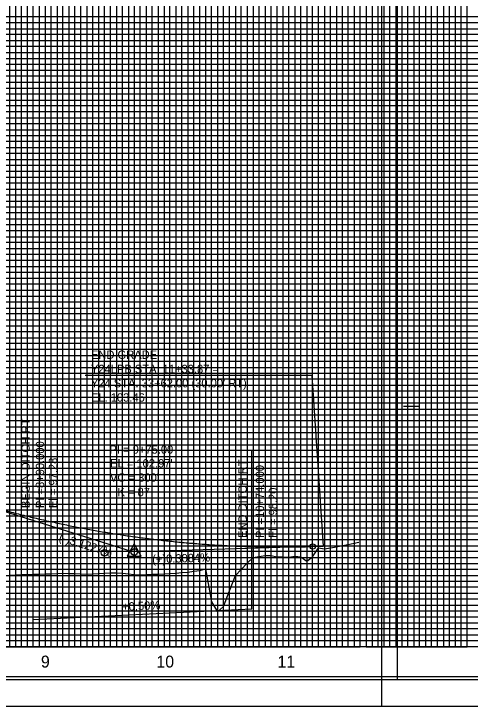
# Model space of a CAD drawing. Extents: x 2345490 to 2436403, y 465165 to 573888.
# Drawn here: x 2411769 to 2412153, y 532446 to 533028 of the extents above; entities that cross this region are included whole.
import ezdxf

# ---------------------------------------------------------------- set-up
doc = ezdxf.new("R2010")
doc.units = 0
for name, color, linetype in [('Old_Level_1', 7, 'Continuous'), ('Old_Level_18', 7, 'Continuous'), ('Old_Level_2', 7, 'Continuous'), ('Old_Level_3', 7, 'Continuous'), ('Old_Level_41', 7, 'Continuous'), ('Old_Level_42', 7, 'Continuous'), ('Old_Level_43', 7, 'Continuous'), ('Old_Level_50', 7, 'Continuous'), ('Old_Level_51', 7, 'Continuous'), ('Old_Level_52', 7, 'Continuous'), ('Old_Level_62', 7, 'Continuous'), ('Old_Level_63', 7, 'Continuous')]:
    doc.layers.add(name, color=color, linetype=linetype)

msp = doc.modelspace()

# ---------------------------------------------------------------- linework, layer by layer
at = {"layer": 'Old_Level_1'}
for points in [[(2411895.325, 532556.85825), (2411900.325, 532557.108), (2411905.325, 532557.51525), (2411910.325, 532557.9225), (2411915.325, 532558.32975), (2411920.325, 532559.0335), (2411925.325, 532559.82575), (2411930.325, 532561.1485), (2411935.325, 532533.47425), (2411940.325, 532525.0015), (2411945.325, 532529.461), (2411950.325, 532542.52475), (2411955.325, 532555.5885), (2411960.325, 532560.59275), (2411965.325, 532565.9155), (2411970.325, 532570.771), (2411975.325, 532571.51625), (2411980.325, 532572.2615), (2411985.325, 532572.44975), (2411990.325, 532571.2615), (2411995.325, 532571.30775), (2412000.325, 532571.033), (2412005.325, 532571.77175), (2412010.325, 532571.3365), (2412015.325, 532567.4515), (2412020.325, 532571.3345), (2412025.325, 532578.781), (2412030.325, 532578.0145), (2412035.325, 532578.869), (2412040.325, 532579.75475), (2412045.325, 532580.64075), (2412050.325, 532581.5265), (2412055.325, 532582.6855), (2412059.195, 532583.5655)], [(2411765.325, 532555.92575), (2411770.325, 532556.10975), (2411775.325, 532556.278), (2411780.325, 532556.40175), (2411785.325, 532556.527), (2411790.325, 532556.66025), (2411795.325, 532556.8405), (2411800.325, 532557.022), (2411805.325, 532557.205), (2411810.325, 532557.39075), (2411815.325, 532557.24025), (2411820.325, 532557.0725), (2411825.325, 532556.90675), (2411830.325, 532556.74225), (2411835.325, 532556.8855), (2411840.325, 532557.17725), (2411845.325, 532557.47), (2411850.325, 532557.7635), (2411855.325, 532557.81475), (2411860.325, 532557.381), (2411865.325, 532556.92175), (2411870.325, 532556.46325), (2411875.325, 532556.15), (2411880.325, 532556.327), (2411885.325, 532556.50425), (2411890.325, 532556.68125), (2411895.325, 532556.85825)]]:
    msp.add_lwpolyline(points, dxfattribs=at)
at = {"layer": 'Old_Level_18'}
msp.add_lwpolyline([(2412345.325, 533520.5875), (2410845.325, 533520.5875), (2410845.325, 532470.5875), (2412345.325, 532470.5875)], close=True, dxfattribs=at)
at = {"layer": 'Old_Level_2'}
for p, q in [((2412019.7535, 532723.708), (2411829.07475, 532723.708)), ((2412019.7535, 532723.708), (2412029.195, 532580.1875)), ((2411720.325, 532622.1275), (2411867.70025, 532576.10725)), ((2412020.325, 532579.914), (2411873.07375, 532575.3725)), ((2412020.325, 532579.914), (2412029.195, 532580.1875))]:
    msp.add_line(p, q, dxfattribs=at)
msp.add_lwpolyline([(2411864.45375, 532571.91225), (2411876.19625, 532571.91225), (2411870.32525, 532582.038)], close=True, dxfattribs=at)
for centre, radius in [((2412020.325, 532579.914), 2.25), ((2411845.325, 532574.5875), 2.75), ((2411870.325, 532575.2875), 2.75)]:
    msp.add_circle(centre, radius, dxfattribs=at)
msp.add_spline([(2411720.325, 532622.1275), (2411726.325, 532620.2745), (2411732.325, 532618.46275), (2411738.325, 532616.692), (2411744.325, 532614.9625), (2411750.325, 532613.27425), (2411756.325, 532611.62725), (2411762.325, 532610.02125), (2411768.325, 532608.45625), (2411774.325, 532606.93275), (2411780.325, 532605.45025), (2411786.325, 532604.009), (2411792.325, 532602.609), (2411798.325, 532601.25), (2411804.325, 532599.93225), (2411810.325, 532598.6555), (2411816.325, 532597.42025), (2411822.325, 532596.226), (2411828.325, 532595.07275), (2411834.325, 532593.961), (2411840.325, 532592.89025), (2411846.325, 532591.86075), (2411852.325, 532590.87225), (2411858.325, 532589.925), (2411864.325, 532589.019), (2411870.325, 532588.15425), (2411876.325, 532587.3305), (2411882.325, 532586.548), (2411888.325, 532585.80675), (2411894.325, 532585.1065), (2411900.325, 532584.4475), (2411906.325, 532583.82975), (2411912.325, 532583.253), (2411918.325, 532582.7175), (2411924.325, 532582.22325), (2411930.325, 532581.77025), (2411936.325, 532581.35825), (2411942.325, 532580.9875), (2411948.325, 532580.65775), (2411954.325, 532580.3695), (2411960.325, 532580.12225), (2411966.325, 532579.916), (2411972.325, 532579.75125), (2411978.325, 532579.6275), (2411984.325, 532579.54475), (2411990.325, 532579.5035), (2411996.325, 532579.50325), (2412002.325, 532579.54425), (2412008.325, 532579.62625), (2412014.325, 532579.7495), (2412020.325, 532579.914)], degree=3, dxfattribs=at)
at = {"layer": 'Old_Level_3'}
for p, q in [((2411785.325, 532518.3875), (2411785.325, 532693.32339)), ((2411969.325, 532600.02989), (2411969.325, 532661.04346)), ((2411969.325, 532527.5875), (2411969.325, 532600.02989)), ((2411785.325, 532518.3875), (2411969.325, 532527.5875))]:
    msp.add_line(p, q, dxfattribs=at)
at = {"layer": 'Old_Level_41'}
for p, q in [((2412096.825, 532698.0875), (2412109.325, 532698.0875)), ((2412345.325, 532495.5875), (2410845.325, 532495.5875))]:
    msp.add_line(p, q, dxfattribs=at)
for points in [[(2411770.325, 533520.5875), (2411770.325, 532495.5875), (2411820.325, 532495.5875), (2411820.325, 533520.5875)], [(2411795.325, 533520.5875), (2411795.325, 532495.5875), (2411845.325, 532495.5875), (2411845.325, 533520.5875)], [(2411870.325, 533520.5875), (2411870.325, 532495.5875), (2411920.325, 532495.5875), (2411920.325, 533520.5875)], [(2411895.325, 533520.5875), (2411895.325, 532495.5875), (2411945.325, 532495.5875), (2411945.325, 533520.5875)], [(2411970.325, 533520.5875), (2411970.325, 532495.5875), (2412020.325, 532495.5875), (2412020.325, 533520.5875)], [(2411995.325, 533520.5875), (2411995.325, 532495.5875), (2412045.325, 532495.5875), (2412045.325, 533520.5875)], [(2412070.325, 533520.5875), (2412070.325, 532495.5875), (2412120.325, 532495.5875), (2412120.325, 533520.5875)], [(2412095.325, 533520.5875), (2412095.325, 532495.5875), (2412145.325, 532495.5875), (2412145.325, 533520.5875)], [(2412345.325, 533020.5875), (2410845.325, 533020.5875), (2410845.325, 532970.5875), (2412345.325, 532970.5875)], [(2412345.325, 532920.5875), (2410845.325, 532920.5875), (2410845.325, 532870.5875), (2412345.325, 532870.5875)], [(2412345.325, 532845.5875), (2410845.325, 532845.5875), (2410845.325, 532895.5875), (2412345.325, 532895.5875)], [(2412345.325, 532820.5875), (2410845.325, 532820.5875), (2410845.325, 532770.5875), (2412345.325, 532770.5875)], [(2412345.325, 532745.5875), (2410845.325, 532745.5875), (2410845.325, 532795.5875), (2412345.325, 532795.5875)], [(2412345.325, 532720.5875), (2410845.325, 532720.5875), (2410845.325, 532670.5875), (2412345.325, 532670.5875)], [(2412345.325, 532620.5875), (2410845.325, 532620.5875), (2410845.325, 532570.5875), (2412345.325, 532570.5875)], [(2412345.325, 532545.5875), (2410845.325, 532545.5875), (2410845.325, 532595.5875), (2412345.325, 532595.5875)], [(2412345.325, 532520.5875), (2410845.325, 532520.5875)]]:
    msp.add_lwpolyline(points, dxfattribs=at)
at = {"layer": 'Old_Level_42'}
for points in [[(2412345.325, 532945.5875), (2410845.325, 532945.5875), (2410845.325, 532995.5875), (2412345.325, 532995.5875)], [(2412345.325, 532645.5875), (2410845.325, 532645.5875), (2410845.325, 532695.5875), (2412345.325, 532695.5875)]]:
    msp.add_lwpolyline(points, dxfattribs=at)
at = {"layer": 'Old_Level_43'}
for points in [[(2411765.325, 533520.5875), (2411765.325, 532495.5875), (2411775.325, 532495.5875), (2411775.325, 533520.5875)], [(2411780.325, 533520.5875), (2411780.325, 532495.5875), (2411785.325, 532495.5875), (2411785.325, 533520.5875)], [(2411790.325, 533520.5875), (2411790.325, 532495.5875), (2411800.325, 532495.5875), (2411800.325, 533520.5875)], [(2411805.325, 533520.5875), (2411805.325, 532495.5875), (2411810.325, 532495.5875), (2411810.325, 533520.5875)], [(2411815.325, 533520.5875), (2411815.325, 532495.5875), (2411825.325, 532495.5875), (2411825.325, 533520.5875)], [(2411830.325, 533520.5875), (2411830.325, 532495.5875), (2411835.325, 532495.5875), (2411835.325, 533520.5875)], [(2411840.325, 533520.5875), (2411840.325, 532495.5875), (2411850.325, 532495.5875), (2411850.325, 533520.5875)], [(2411855.325, 533520.5875), (2411855.325, 532495.5875), (2411860.325, 532495.5875), (2411860.325, 533520.5875)], [(2411865.325, 533520.5875), (2411865.325, 532495.5875), (2411875.325, 532495.5875), (2411875.325, 533520.5875)], [(2411880.325, 533520.5875), (2411880.325, 532495.5875), (2411885.325, 532495.5875), (2411885.325, 533520.5875)], [(2411890.325, 533520.5875), (2411890.325, 532495.5875), (2411900.325, 532495.5875), (2411900.325, 533520.5875)], [(2411905.325, 533520.5875), (2411905.325, 532495.5875), (2411910.325, 532495.5875), (2411910.325, 533520.5875)], [(2411915.325, 533520.5875), (2411915.325, 532495.5875)], [(2411915.325, 532495.5875), (2411925.325, 532495.5875), (2411925.325, 533520.5875)], [(2411930.325, 533520.5875), (2411930.325, 532495.5875), (2411935.325, 532495.5875), (2411935.325, 533520.5875)], [(2411940.325, 533520.5875), (2411940.325, 532495.5875), (2411950.325, 532495.5875), (2411950.325, 533520.5875)], [(2411955.325, 533520.5875), (2411955.325, 532495.5875), (2411960.325, 532495.5875), (2411960.325, 533520.5875)], [(2411965.325, 533520.5875), (2411965.325, 532495.5875), (2411975.325, 532495.5875), (2411975.325, 533520.5875)], [(2411980.325, 533520.5875), (2411980.325, 532495.5875), (2411985.325, 532495.5875), (2411985.325, 533520.5875)], [(2411990.325, 533520.5875), (2411990.325, 532495.5875), (2412000.325, 532495.5875), (2412000.325, 533520.5875)], [(2412005.325, 533520.5875), (2412005.325, 532495.5875), (2412010.325, 532495.5875), (2412010.325, 533520.5875)], [(2412015.325, 533520.5875), (2412015.325, 532495.5875), (2412025.325, 532495.5875), (2412025.325, 533520.5875)], [(2412030.325, 533520.5875), (2412030.325, 532495.5875), (2412035.325, 532495.5875), (2412035.325, 533520.5875)], [(2412040.325, 533520.5875), (2412040.325, 532495.5875), (2412050.325, 532495.5875), (2412050.325, 533520.5875)], [(2412055.325, 533520.5875), (2412055.325, 532495.5875), (2412060.325, 532495.5875), (2412060.325, 533520.5875)], [(2412065.325, 533520.5875), (2412065.325, 532495.5875), (2412075.325, 532495.5875), (2412075.325, 533520.5875)], [(2412080.325, 533520.5875), (2412080.325, 532495.5875), (2412085.325, 532495.5875), (2412085.325, 533520.5875)], [(2412090.325, 533520.5875), (2412090.325, 532495.5875), (2412100.325, 532495.5875), (2412100.325, 533520.5875)], [(2412105.325, 533520.5875), (2412105.325, 532495.5875), (2412110.325, 532495.5875), (2412110.325, 533520.5875)], [(2412115.325, 533520.5875), (2412115.325, 532495.5875), (2412125.325, 532495.5875), (2412125.325, 533520.5875)], [(2412130.325, 533520.5875), (2412130.325, 532495.5875), (2412135.325, 532495.5875), (2412135.325, 533520.5875)], [(2412140.325, 533520.5875), (2412140.325, 532495.5875), (2412150.325, 532495.5875), (2412150.325, 533383.0375)], [(2412295.325, 533025.5875), (2410895.325, 533025.5875), (2410895.325, 533015.5875), (2412295.325, 533015.5875)], [(2412295.325, 533010.5875), (2410895.325, 533010.5875), (2410895.325, 533005.5875), (2412295.325, 533005.5875)], [(2412295.325, 533000.5875), (2410895.325, 533000.5875)], [(2410895.325, 532990.5875), (2412295.325, 532990.5875)], [(2412295.325, 532985.5875), (2410895.325, 532985.5875), (2410895.325, 532980.5875), (2412295.325, 532980.5875)], [(2412295.325, 532975.5875), (2410895.325, 532975.5875), (2410895.325, 532965.5875), (2412295.325, 532965.5875)], [(2412295.325, 532960.5875), (2410895.325, 532960.5875), (2410895.325, 532955.5875), (2412295.325, 532955.5875)], [(2412295.325, 532950.5875), (2410895.325, 532950.5875), (2410895.325, 532940.5875), (2412295.325, 532940.5875)], [(2412295.325, 532935.5875), (2410895.325, 532935.5875), (2410895.325, 532930.5875), (2412295.325, 532930.5875)], [(2412295.325, 532925.5875), (2410895.325, 532925.5875), (2410895.325, 532915.5875), (2412295.325, 532915.5875)], [(2412295.325, 532910.5875), (2410895.325, 532910.5875), (2410895.325, 532905.5875), (2412295.325, 532905.5875)], [(2412295.325, 532900.5875), (2410895.325, 532900.5875), (2410895.325, 532890.5875), (2412295.325, 532890.5875)], [(2412295.325, 532885.5875), (2410895.325, 532885.5875), (2410895.325, 532880.5875), (2412295.325, 532880.5875)], [(2412295.325, 532875.5875), (2410895.325, 532875.5875), (2410895.325, 532865.5875), (2412295.325, 532865.5875)], [(2412295.325, 532860.5875), (2410895.325, 532860.5875), (2410895.325, 532855.5875), (2412295.325, 532855.5875)], [(2412295.325, 532850.5875), (2410895.325, 532850.5875), (2410895.325, 532840.5875), (2412295.325, 532840.5875)], [(2412295.325, 532835.5875), (2410895.325, 532835.5875), (2410895.325, 532830.5875), (2412295.325, 532830.5875)], [(2412295.325, 532825.5875), (2410895.325, 532825.5875), (2410895.325, 532815.5875), (2412295.325, 532815.5875)], [(2412295.325, 532810.5875), (2410895.325, 532810.5875), (2410895.325, 532805.5875), (2412295.325, 532805.5875)], [(2412295.325, 532800.5875), (2410895.325, 532800.5875), (2410895.325, 532790.5875), (2412295.325, 532790.5875)], [(2412295.325, 532785.5875), (2410895.325, 532785.5875), (2410895.325, 532780.5875), (2412295.325, 532780.5875)], [(2412295.325, 532775.5875), (2410895.325, 532775.5875), (2410895.325, 532765.5875), (2412295.325, 532765.5875)], [(2412295.325, 532760.5875), (2410895.325, 532760.5875), (2410895.325, 532755.5875), (2412295.325, 532755.5875)], [(2412295.325, 532750.5875), (2410895.325, 532750.5875), (2410895.325, 532740.5875), (2412295.325, 532740.5875)], [(2412295.325, 532735.5875), (2410895.325, 532735.5875), (2410895.325, 532730.5875), (2412295.325, 532730.5875)], [(2412295.325, 532725.5875), (2410895.325, 532725.5875), (2410895.325, 532715.5875), (2412295.325, 532715.5875)], [(2412295.325, 532710.5875), (2410895.325, 532710.5875), (2410895.325, 532705.5875), (2412295.325, 532705.5875)], [(2412295.325, 532700.5875), (2410895.325, 532700.5875)], [(2410895.325, 532690.5875), (2412295.325, 532690.5875)], [(2412295.325, 532685.5875), (2410895.325, 532685.5875), (2410895.325, 532680.5875), (2412295.325, 532680.5875)], [(2412295.325, 532675.5875), (2410895.325, 532675.5875)], [(2410895.325, 532665.5875), (2412295.325, 532665.5875)], [(2412295.325, 532660.5875), (2410895.325, 532660.5875), (2410895.325, 532655.5875), (2412295.325, 532655.5875)], [(2412295.325, 532650.5875), (2410895.325, 532650.5875), (2410895.325, 532640.5875), (2412295.325, 532640.5875)], [(2412295.325, 532635.5875), (2410895.325, 532635.5875), (2410895.325, 532630.5875), (2412295.325, 532630.5875)], [(2412295.325, 532625.5875), (2410895.325, 532625.5875), (2410895.325, 532615.5875), (2412295.325, 532615.5875)], [(2412295.325, 532610.5875), (2410895.325, 532610.5875), (2410895.325, 532605.5875), (2412295.325, 532605.5875)], [(2412295.325, 532600.5875), (2410895.325, 532600.5875), (2410895.325, 532590.5875), (2412295.325, 532590.5875)], [(2412295.325, 532585.5875), (2410895.325, 532585.5875), (2410895.325, 532580.5875), (2412295.325, 532580.5875)], [(2412295.325, 532575.5875), (2410895.325, 532575.5875), (2410895.325, 532565.5875), (2412295.325, 532565.5875)], [(2412295.325, 532560.5875), (2410895.325, 532560.5875), (2410895.325, 532555.5875), (2412295.325, 532555.5875)], [(2412295.325, 532550.5875), (2410895.325, 532550.5875), (2410895.325, 532540.5875), (2412295.325, 532540.5875)], [(2412295.325, 532535.5875), (2410895.325, 532535.5875), (2410895.325, 532530.5875), (2412295.325, 532530.5875)], [(2412295.325, 532525.5875), (2410895.325, 532525.5875), (2410895.325, 532515.5875), (2412295.325, 532515.5875)], [(2412295.325, 532510.5875), (2410895.325, 532510.5875), (2410895.325, 532505.5875), (2412295.325, 532505.5875)], [(2412295.325, 532500.5875), (2410895.325, 532500.5875)]]:
    msp.add_lwpolyline(points, dxfattribs=at)
at = {"layer": 'Old_Level_50'}
msp.add_line((2412078.325, 532445.5875), (2412078.325, 532445.5875), dxfattribs=at)
for points in [[(2412357.825, 533523.1375), (2410691.325, 533523.1375), (2410691.325, 532468.0375), (2412357.825, 532468.0375)], [(2413757.825, 533523.1375), (2412091.325, 533523.1375), (2412091.325, 532468.0375), (2413757.825, 532468.0375)]]:
    msp.add_lwpolyline(points, close=True, dxfattribs=at)
at = {"layer": 'Old_Level_51'}
for points in [[(2412362.325, 533545.5875), (2410678.325, 533545.5875), (2410678.325, 532445.5875), (2412362.325, 532445.5875)], [(2413762.325, 533545.5875), (2412078.325, 533545.5875), (2412078.325, 532445.5875), (2413762.325, 532445.5875)]]:
    msp.add_lwpolyline(points, close=True, dxfattribs=at)
at = {"layer": 'Old_Level_52'}
msp.add_line((2412091.325, 532468.0375), (2412091.325, 532468.0375), dxfattribs=at)
at = {"layer": 'Old_Level_63'}
msp.add_line((2410895.325, 532495.5875), (2412059.1905, 532495.5875), dxfattribs=at)

# ---------------------------------------------------------------- texts
at = {"layer": 'Old_Level_2'}
for s, height, p in [('END GRADE', 7.000001, (2411833.85075, 532737.8165)), ('Y24LPB STA. 11+33.87 =', 7.0000005, (2411833.85075, 532725.8165)), ("Y24 STA. 33+62.00 (30.00' RT)", 7.0000005, (2411833.85075, 532713.8165)), ('EL. 103.46', 7.000001, (2411833.85075, 532701.8165)), ('PI = 9+75.00', 7.0000005, (2411849.46775, 532658.0305)), ("EL = 102.97'", 7.0000005, (2411849.9915, 532646.41375)), ("VC = 300'", 7.000001, (2411849.89725, 532634.462)), ('K = 87', 7.000001, (2411856.18275, 532622.263))]:
    msp.add_text(s, height=height, dxfattribs=at).set_placement(p)
for s, rotation, p in [('(-)3.1227%', 342.65815556, (2411806.38575, 532584.77775)), ('(+)0.3084%', 1.76660278, (2411885.49725, 532565.751))]:
    msp.add_text(s, height=7.000001, rotation=rotation, dxfattribs=at).set_placement(p)
at = {"layer": 'Old_Level_3'}
for s, height, rotation, p in [('BEGIN DITCH RT', 7.0000005, 90, (2411782.35653, 532612.235)), ('PI =8+90.000', 7.0000005, 90, (2411794.4624, 532612.235)), ('El = 97.28', 7.000001, 90, (2411805.4624, 532612.235)), ('END DITCH RT', 7.0000005, 90, (2411964.90383, 532587.05433)), ('PI =10+74.000', 7.0000005, 90, (2411979.43087, 532587.05433)), ('El = 98.20', 7.000001, 90, (2411990.43087, 532587.05433)), ('+0.50%', 7.000001, 2.8624, (2411860.31525, 532525.68825))]:
    msp.add_text(s, height=height, rotation=rotation, dxfattribs=at).set_placement(p)
at = {"layer": 'Old_Level_62'}
for s, height, p in [('9', 10, (2411791.79025, 532478.0875)), ('10', 10.000001, (2411888.9085, 532478.0875)), ('11', 10.000001, (2411990.748, 532478.0875))]:
    msp.add_text(s, height=height, dxfattribs=at).set_placement(p)

doc.saveas('drawing.dxf')
